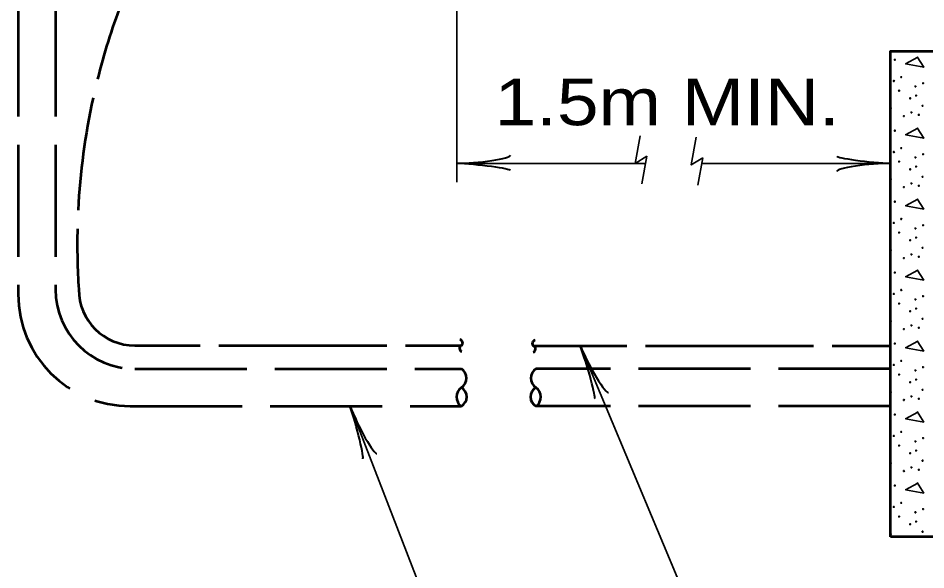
# Model space of a CAD drawing. Extents: x -24 to 689, y -7 to 446.
# Drawn here: x 342.74 to 391.38, y 76.85 to 106.38 of the extents above; entities that cross this region are included whole.
import ezdxf
from ezdxf.enums import TextEntityAlignment as Align

# ---------------------------------------------------------------- set-up
doc = ezdxf.new("R2010")
doc.units = 0
doc.linetypes.add('LONG_DASHED', pattern=[7.5, 6, -1.5])
doc.layers.add('1', color=7, linetype='Continuous', lineweight=35)

msp = doc.modelspace()

# ---------------------------------------------------------------- linework, layer by layer
at = {"layer": '1', "linetype": 'LONG_DASHED', "lineweight": 53}
for p, q in [((342.736, 129.608), (342.736, 91.608)), ((344.736, 129.608), (344.736, 91.858)), ((348.986, 87.608), (366.486, 87.608)), ((389.486, 87.608), (370.486, 87.608)), ((348.736, 85.608), (366.486, 85.608)), ((389.486, 85.608), (370.486, 85.608))]:
    msp.add_line(p, q, dxfattribs=at)
at = {"layer": '1'}
for p, q in [((366.236, 122.608), (366.236, 97.608)), ((376.061, 100.084), (375.8, 98.606)), ((375.8, 98.606), (376.419, 98.989)), ((376.419, 98.989), (376.159, 97.512)), ((379.426, 98.912), (379.165, 97.435)), ((366.236, 98.608), (376.361, 98.608)), ((379.361, 98.608), (389.486, 98.608)), ((372.863, 88.827), (381.229, 68.89)), ((360.525, 85.608), (372.352, 55.053))]:
    msp.add_line(p, q, dxfattribs=at)
at = {"layer": '1', "lineweight": 53}
for p, q in [((348.986, 88.858), (352.486, 88.858)), ((353.486, 88.858), (362.486, 88.858)), ((363.486, 88.858), (366.486, 88.858)), ((375.363, 88.827), (370.363, 88.827)), ((385.363, 88.827), (376.363, 88.827)), ((389.486, 88.827), (386.363, 88.827))]:
    msp.add_line(p, q, dxfattribs=at)
msp.add_lwpolyline([(389.486, 78.608), (389.486, 104.608), (415.486, 104.608), (415.486, 78.608)], close=True, dxfattribs=at)
at = {"layer": '1'}
for points in [[(390.95, 104.296), (390.29, 103.936), (391.27, 103.756), (390.91, 104.316)], [(390.95, 100.496), (390.29, 100.136), (391.27, 99.956), (390.91, 100.516)], [(379.067, 100.006), (378.807, 98.529), (379.426, 98.912)], [(390.95, 96.696), (390.29, 96.336), (391.27, 96.156), (390.91, 96.716)], [(390.95, 92.896), (390.29, 92.536), (391.27, 92.356), (390.91, 92.916)], [(390.95, 89.096), (390.29, 88.736), (391.27, 88.556), (390.91, 89.116)], [(390.95, 85.296), (390.29, 84.936), (391.27, 84.756), (390.91, 85.316)], [(390.95, 81.496), (390.29, 81.136), (391.27, 80.956), (390.91, 81.516)]]:
    msp.add_lwpolyline(points, dxfattribs=at)
for centre in [(389.716, 104.158), (390.061, 103.229), (389.663, 103.017), (390.816, 102.726), (391.227, 102.898), (389.941, 102.5), (390.856, 102.235), (390.538, 102.089), (391.2, 101.692), (390.604, 101.334), (391.002, 101.206), (390.206, 101.14), (389.716, 100.358), (389.663, 99.217), (390.061, 99.429), (390.816, 98.926), (391.227, 99.098), (389.941, 98.7), (390.538, 98.289), (390.856, 98.435), (391.2, 97.892), (390.206, 97.34), (390.604, 97.534), (391.002, 97.406), (389.716, 96.558), (389.663, 95.417), (390.061, 95.629), (389.941, 94.9), (390.816, 95.126), (391.227, 95.298), (390.538, 94.489), (390.856, 94.635), (391.2, 94.092), (390.206, 93.54), (390.604, 93.734), (391.002, 93.606), (389.716, 92.758), (389.663, 91.617), (390.061, 91.829), (391.227, 91.498), (389.941, 91.1), (390.816, 91.326), (390.538, 90.689), (390.856, 90.835), (391.2, 90.292), (390.206, 89.74), (390.604, 89.934), (391.002, 89.806), (389.716, 88.958), (390.061, 88.029), (389.663, 87.817), (391.227, 87.698), (389.941, 87.3), (390.816, 87.526), (390.538, 86.889), (390.856, 87.035), (390.604, 86.134), (391.2, 86.492), (390.206, 85.94), (391.002, 86.006), (389.716, 85.158), (390.061, 84.229), (389.663, 84.017), (390.816, 83.726), (391.227, 83.898), (389.941, 83.5), (390.856, 83.235), (390.538, 83.089), (391.2, 82.692), (390.604, 82.334), (391.002, 82.206), (390.206, 82.14), (389.716, 81.358), (390.061, 80.429), (389.663, 80.217), (390.816, 79.926), (391.227, 80.098), (389.941, 79.7), (390.538, 79.289), (390.856, 79.435), (391.2, 78.892)]:
    msp.add_circle(centre, 0.0265, dxfattribs=at)
at = {"layer": '1', "lineweight": 53}
for centre, radius, start, end in [((382.177, 94.31), 36.274, 159.3392, 165.9622), ((382.177, 94.31), 36.274, 167.5848, 177.1578), ((382.177, 94.31), 36.274, 178.7384, 183.8749), ((348.986, 91.858), 3, 180, 270), ((366.388, 89), 0.172, 304.5563, 83.6232), ((370.461, 88.969), 0.172, 96.3768, 235.4437), ((366.558, 88.701), 0.172, 114.6193, 253.6863), ((370.291, 88.67), 0.172, 286.3137, 65.3807), ((366.178, 87.108), 0.587, 301.6319, 58.3681), ((370.794, 87.108), 0.587, 121.6319, 238.3681), ((366.833, 86.108), 0.609, 124.7655, 235.2345), ((366.204, 86.108), 0.574, 299.3912, 60.6088), ((370.767, 86.108), 0.574, 119.3912, 240.6088), ((370.139, 86.108), 0.609, 304.7655, 55.2345)]:
    msp.add_arc(centre, radius, start, end, dxfattribs=at)
at = {"layer": '1'}
for centre in [(389.504, 101.559), (389.504, 97.759), (389.504, 93.959), (389.504, 90.159), (389.504, 86.359), (389.504, 82.559), (389.504, 78.759)]:
    msp.add_arc(centre, 0.0265, 226.4481, 133.5519, dxfattribs=at)
at = {"layer": '1', "linetype": 'LONG_DASHED', "lineweight": 53}
for centre, radius in [((348.736, 91.608), 6), ((348.986, 91.858), 4.25)]:
    msp.add_arc(centre, radius, 180, 270, dxfattribs=at)
at = {"layer": '1', "lineweight": 40}
for centre, major_axis, ratio, start_param, end_param in [((367.327, 98.885), (-1.786, -0.156), 0.122415, 0.896353, 3.141593), ((367.327, 98.885), (-1.786, -0.156), 0.122415, 0.896353, 3.141593), ((388.365, 98.82), (1.756, -0.176), 0.07063, 3.140715, 5.41811), ((388.365, 98.82), (1.756, -0.176), 0.07063, 3.140715, 5.41811), ((367.356, 98.397), (-1.756, 0.176), 0.07063, 3.140715, 5.41811), ((367.356, 98.397), (-1.756, 0.176), 0.07063, 3.140715, 5.41811), ((388.395, 98.332), (1.786, 0.156), 0.122415, 0.896353, 3.141593), ((388.395, 98.332), (1.786, 0.156), 0.122415, 0.896353, 3.141593), ((373.102, 87.712), (0.518, -1.688), 0.07063, 6.282307, 8.559703), ((373.102, 87.712), (0.518, -1.688), 0.07063, 6.282307, 8.559703), ((373.54, 87.928), (-0.835, 1.586), 0.122415, 0.896353, 3.141593), ((373.54, 87.928), (-0.835, 1.586), 0.122415, 0.896353, 3.141593), ((360.732, 84.487), (-0.47, 1.701), 0.07063, 3.140715, 5.41811), ((361.176, 84.69), (-0.79, 1.609), 0.122415, 0.896353, 3.141593)]:
    msp.add_ellipse(centre, major_axis=major_axis, ratio=ratio, start_param=start_param, end_param=end_param, dxfattribs=at)

# ---------------------------------------------------------------- texts
at = {"layer": '1', "width": 1.2}
msp.add_text('1.5m MIN.', height=2.5, dxfattribs=at).set_placement((377.515, 100.65), align=Align.CENTER)

doc.saveas('drawing.dxf')
